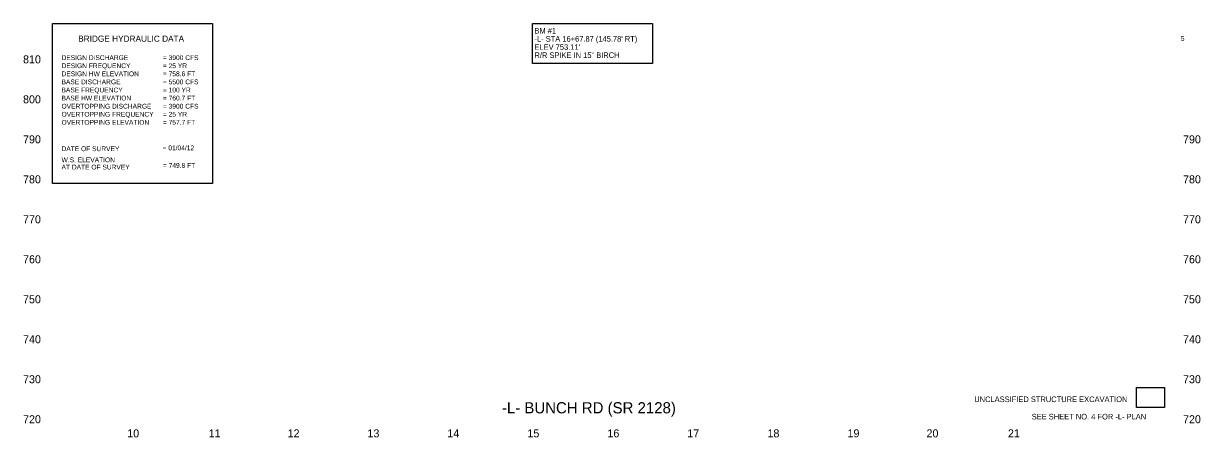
# Model space of a CAD drawing. Extents: x 114 to 1585, y -18 to 500.
import ezdxf

# ---------------------------------------------------------------- set-up
doc = ezdxf.new("R2010")
doc.units = 0
for name, color, linetype in [('Default', 7, 'Continuous'), ('Exist Profile Cell', 7, 'Continuous'), ('Exist Vertical Profile Ground Line', 7, 'Continuous'), ('Exist Vertical Profile Horizontal Axis Label Major', 7, 'Continuous'), ('Exist Vertical Profile Vertical Axis Label', 7, 'Continuous'), ('Scratch_Level_1', 7, 'Continuous'), ('Scratch_Level_2', 7, 'Continuous')]:
    doc.layers.add(name, color=color, linetype=linetype)

msp = doc.modelspace()

# ---------------------------------------------------------------- linework, layer by layer
at = {"layer": 'Default'}
msp.add_lwpolyline([(750, 500), (900, 500), (900, 450), (750, 450)], close=True, dxfattribs=at)
at = {"layer": 'Exist Vertical Profile Horizontal Axis Label Major'}
msp.add_lwpolyline([(1505, 45), (1540, 45), (1540, 20), (1505, 20)], close=True, dxfattribs=at)
at = {"layer": 'Scratch_Level_2'}
msp.add_lwpolyline([(150, 500), (350, 500), (350, 300), (150, 300)], close=True, dxfattribs=at)

# ---------------------------------------------------------------- texts
at = {"layer": 'Exist Profile Cell'}
for s, p in [('810', (113.4, 450.2)), ('800', (113.4, 400.2)), ('790', (113.4, 350.2)), ('790', (1563, 350.2)), ('780', (113.4, 300.2)), ('780', (1563, 300.2)), ('770', (113.4, 250.2)), ('770', (1563, 250.2)), ('760', (113.4, 200.2)), ('760', (1563, 200.2)), ('750', (113.4, 150.2)), ('750', (1563, 150.2)), ('740', (113.4, 100.2)), ('740', (1563, 100.2)), ('730', (113.4, 50.2)), ('730', (1563, 50.2)), ('720', (113.4, 0.2)), ('720', (1563, 0.2))]:
    msp.add_text(s, height=10, dxfattribs=at).set_placement(p)
at = {"layer": 'Exist Vertical Profile Ground Line'}
for s, p in [('10', (243.6, -17.5)), ('11', (345.4, -17.5)), ('12', (444, -17.5)), ('13', (543.8, -17.5)), ('14', (643.6, -17.5)), ('15', (743.7, -17.5)), ('16', (843.7, -17.5)), ('17', (943.5, -17.5)), ('18', (1043.7, -17.5)), ('19', (1143.7, -17.5)), ('20', (1242.4, -17.5)), ('21', (1344.2, -17.5))]:
    msp.add_text(s, height=10, dxfattribs=at).set_placement(p)
at = {"layer": 'Exist Vertical Profile Horizontal Axis Label Major'}
msp.add_text('-L- BUNCH RD (SR 2128)', height=14, dxfattribs=at).set_placement((711.8, 12.5))
at = {"layer": 'Exist Vertical Profile Vertical Axis Label'}
for s, p in [('BM #1', (752.5, 487.5)), ("-L- STA 16+67.87 (145.78' RT)", (752.5, 477.3)), ("ELEV 753.11'", (752.5, 467.1)), ('R/R SPIKE IN 15" BIRCH', (752.5, 456.9)), ('UNCLASSIFIED STRUCTURE EXCAVATION', (1302.1, 26.6)), ('SEE SHEET NO. 4 FOR -L- PLAN', (1373.9, 4.9))]:
    msp.add_text(s, height=7, dxfattribs=at).set_placement(p)
at = {"layer": 'Scratch_Level_1'}
msp.add_text('5', height=6, dxfattribs=at).set_placement((1560.2, 478.3))
at = {"layer": 'Scratch_Level_2'}
for s, height, p in [('BRIDGE HYDRAULIC DATA', 7.714, (182.3, 477.2)), ('DESIGN DISCHARGE', 6, (161.5, 454.3)), ('= 3900 CFS', 6, (288.2, 454.3)), ('DESIGN FREQUENCY', 6, (161.5, 444.2)), ('= 25 YR', 6, (288.2, 444.2)), ('DESIGN HW ELEVATION', 6, (161.5, 434.1)), ('BASE DISCHARGE', 6, (161.5, 424)), ('= 758.6 FT', 6, (288.2, 434.1)), ('= 5500 CFS', 6, (288.2, 424)), ('BASE FREQUENCY', 6, (161.5, 413.9)), ('= 100 YR', 6, (288.2, 413.9)), ('OVERTOPPING DISCHARGE', 6, (161.5, 393.6)), ('BASE HW ELEVATION', 6, (161.5, 403.8)), ('= 760.7 FT', 6, (288.2, 403.8)), ('= 3900 CFS', 6, (288.2, 393.6)), ('OVERTOPPING FREQUENCY', 6, (161.5, 383.5)), ('= 25 YR', 6, (288.2, 383.5)), ('OVERTOPPING ELEVATION', 6, (161.5, 373.4)), ('= 757.7 FT', 6, (288.2, 373.4)), ('DATE OF SURVEY', 6, (161.5, 340.4)), ('= 01/04/12', 6, (287.8, 341.5)), ('W.S. ELEVATION', 6, (161.5, 326.5)), ('AT DATE OF SURVEY', 6, (161.5, 317.5)), ('= 749.8 FT', 6, (288.2, 319.5))]:
    msp.add_text(s, height=height, dxfattribs=at).set_placement(p)

doc.saveas('drawing.dxf')
